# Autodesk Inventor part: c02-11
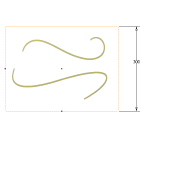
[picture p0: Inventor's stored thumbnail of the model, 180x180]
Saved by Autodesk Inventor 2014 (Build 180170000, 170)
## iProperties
Created: 2013-02
Part Number: c02-11
Material: Generic
Document SubType Name: Modeling
Designer: Thom Tremblay
Density: 1 g/cm^3
Appearance: Default
Author: Thom Tremblay
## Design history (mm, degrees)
sketch "Sketch1"
  geometry: L1 (-200, 150)-(200, 150); L2 (200, 150)-(200, -150); L3 (200, -150)-(-200, -150); L4 (-200, -150)-(-200, 150); 3 further points; 1 other entity
  constraints: 2 midpoint, 1 horizontal alignment, 1 vertical alignment, 2 other
  dimensions: "d1" = 300 dimension on point (0, 0) L1.start L2.end L1.end L3.end L1 L2 L3 L4 point (-200, 0) point (0, -150); "d1" = 300 distance of L1.end L2.end
  node "Image1"
